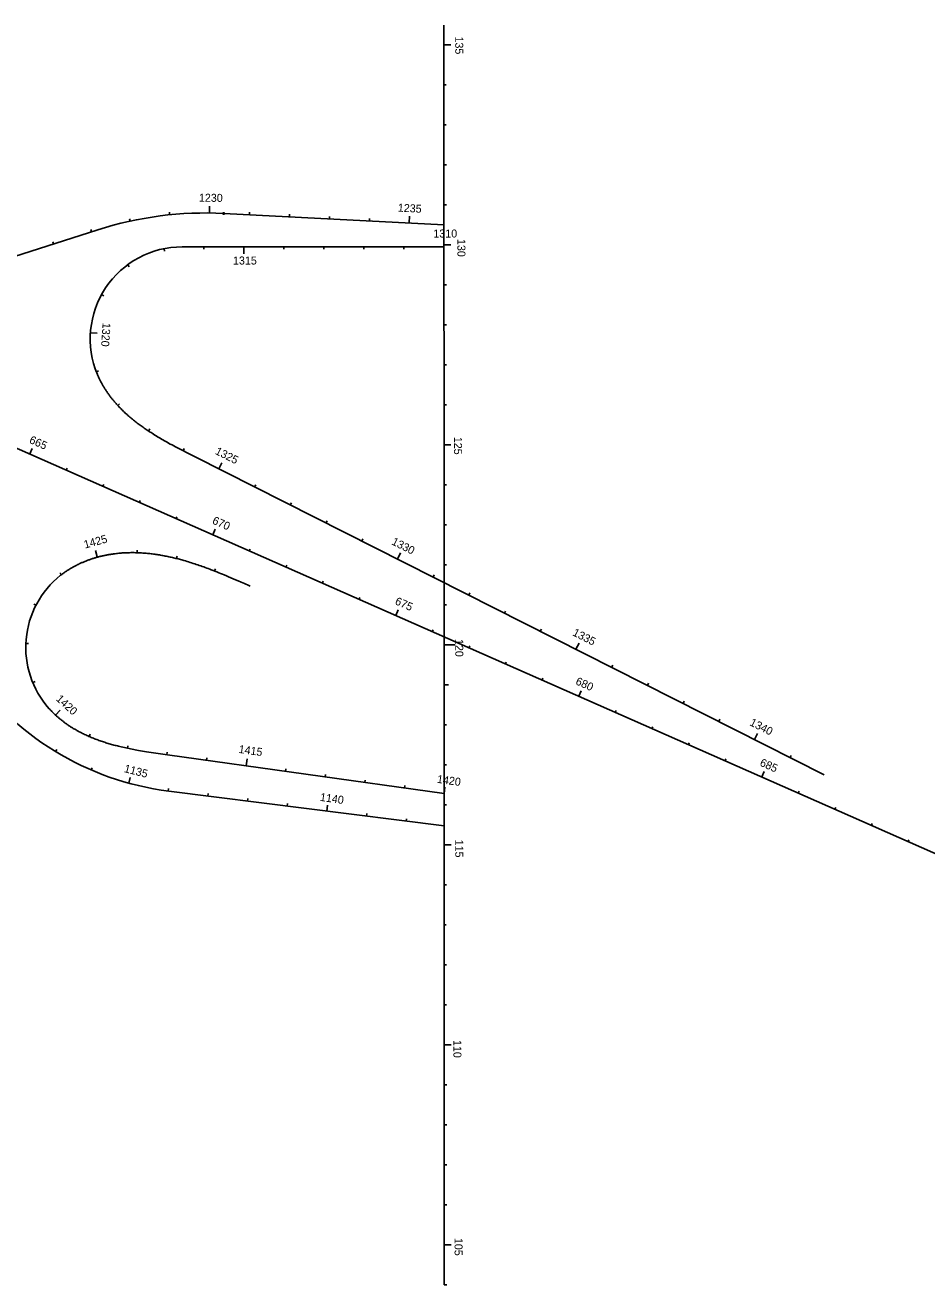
# Model space of a CAD drawing. Extents: x 448091 to 665917, y 1461380 to 1587607.
# Drawn here: x 525049 to 527302, y 1466775 to 1469924 of the extents above; entities that cross this region are included whole.
import ezdxf

# ---------------------------------------------------------------- set-up
doc = ezdxf.new("R2010")
doc.units = 0
doc.layers.add('TextShtNo', color=7, linetype='Continuous')
doc.layers.add('TextTitle', color=7, linetype='Continuous')

msp = doc.modelspace()

# ---------------------------------------------------------------- linework, layer by layer
at = {"layer": 'TextShtNo'}
for p, q in [((526095.6, 1468394.8), (526095, 1469923.7)), ((526095.2, 1469425), (525544.8, 1469453.2)), ((525230.2, 1469412.2), (524834, 1469284.9)), ((525441, 1469369.5), (526095.2, 1469369.8)), ((525230.9, 1469046.2), (525230.1, 1469048)), ((525231.8, 1469044.3), (525230.9, 1469046.2)), ((525232.6, 1469042.5), (525231.8, 1469044.3)), ((525233.5, 1469040.7), (525232.6, 1469042.5)), ((525234.3, 1469038.9), (525233.5, 1469040.7)), ((525235.2, 1469037.1), (525234.3, 1469038.9)), ((525236.1, 1469035.4), (525235.2, 1469037.1)), ((525237, 1469033.6), (525236.1, 1469035.4)), ((525238, 1469031.8), (525237, 1469033.6)), ((525238.9, 1469030), (525238, 1469031.8)), ((525239.9, 1469028.3), (525238.9, 1469030)), ((525240.8, 1469026.5), (525239.9, 1469028.3)), ((525241.8, 1469024.8), (525240.8, 1469026.5)), ((525242.8, 1469023), (525241.8, 1469024.8)), ((525243.8, 1469021.3), (525242.8, 1469023)), ((525244.8, 1469019.6), (525243.8, 1469021.3)), ((525245.9, 1469017.9), (525244.8, 1469019.6)), ((525246.9, 1469016.2), (525245.9, 1469017.9)), ((525248, 1469014.5), (525246.9, 1469016.2)), ((525249.1, 1469012.8), (525248, 1469014.5)), ((525250.2, 1469011.1), (525249.1, 1469012.8)), ((525251.3, 1469009.4), (525250.2, 1469011.1)), ((525252.4, 1469007.8), (525251.3, 1469009.4)), ((525253.5, 1469006.1), (525252.4, 1469007.8)), ((525254.6, 1469004.5), (525253.5, 1469006.1)), ((525255.8, 1469002.8), (525254.6, 1469004.5)), ((525256.9, 1469001.2), (525255.8, 1469002.8)), ((525258.1, 1468999.6), (525256.9, 1469001.2)), ((525259.3, 1468998), (525258.1, 1468999.6)), ((525260.5, 1468996.4), (525259.3, 1468998)), ((525261.7, 1468994.8), (525260.5, 1468996.4)), ((525262.9, 1468993.2), (525261.7, 1468994.8)), ((525264.2, 1468991.6), (525262.9, 1468993.2)), ((525265.4, 1468990), (525264.2, 1468991.6)), ((525266.6, 1468988.5), (525265.4, 1468990)), ((525267.9, 1468986.9), (525266.6, 1468988.5)), ((525269.2, 1468985.4), (525267.9, 1468986.9)), ((525270.5, 1468983.8), (525269.2, 1468985.4)), ((525271.7, 1468982.3), (525270.5, 1468983.8)), ((525273, 1468980.8), (525271.7, 1468982.3)), ((525274.4, 1468979.3), (525273, 1468980.8)), ((525275.7, 1468977.8), (525274.4, 1468979.3)), ((525277, 1468976.3), (525275.7, 1468977.8)), ((525278.3, 1468974.8), (525277, 1468976.3)), ((525279.7, 1468973.3), (525278.3, 1468974.8)), ((525281.7, 1468971.1), (525279.7, 1468973.3)), ((525283.8, 1468968.9), (525281.7, 1468971.1)), ((525285.9, 1468966.8), (525283.8, 1468968.9)), ((525288, 1468964.6), (525285.9, 1468966.8)), ((525290.1, 1468962.5), (525288, 1468964.6)), ((525292.2, 1468960.4), (525290.1, 1468962.5)), ((525294.4, 1468958.3), (525292.2, 1468960.4)), ((525296.6, 1468956.2), (525294.4, 1468958.3)), ((525298.7, 1468954.2), (525296.6, 1468956.2)), ((525300.9, 1468952.2), (525298.7, 1468954.2)), ((525303.2, 1468950.1), (525300.9, 1468952.2)), ((525305.4, 1468948.1), (525303.2, 1468950.1)), ((525307.7, 1468946.2), (525305.4, 1468948.1)), ((525309.9, 1468944.2), (525307.7, 1468946.2)), ((525312.2, 1468942.3), (525309.9, 1468944.2)), ((525314.5, 1468940.3), (525312.2, 1468942.3)), ((525316.8, 1468938.4), (525314.5, 1468940.3)), ((525319.1, 1468936.5), (525316.8, 1468938.4)), ((525321.5, 1468934.6), (525319.1, 1468936.5)), ((525323.8, 1468932.8), (525321.5, 1468934.6)), ((525326.2, 1468930.9), (525323.8, 1468932.8)), ((525328.6, 1468929.1), (525326.2, 1468930.9)), ((525331, 1468927.3), (525328.6, 1468929.1)), ((525333.4, 1468925.5), (525331, 1468927.3)), ((525335.8, 1468923.7), (525333.4, 1468925.5)), ((525338.2, 1468922), (525335.8, 1468923.7)), ((525340.7, 1468920.2), (525338.2, 1468922)), ((525343.1, 1468918.5), (525340.7, 1468920.2)), ((525345.6, 1468916.7), (525343.1, 1468918.5)), ((525348, 1468915), (525345.6, 1468916.7)), ((525350.5, 1468913.3), (525348, 1468915)), ((525353, 1468911.7), (525350.5, 1468913.3)), ((525355.5, 1468910), (525353, 1468911.7)), ((525358, 1468908.3), (525355.5, 1468910)), ((525360.5, 1468906.7), (525358, 1468908.3)), ((525363, 1468905.1), (525360.5, 1468906.7)), ((525365.5, 1468903.5), (525363, 1468905.1)), ((525368.9, 1468901.3), (525365.5, 1468903.5)), ((524956.6, 1468897.4), (528389.9, 1467382.4)), ((525372.3, 1468899.2), (525368.9, 1468901.3)), ((525375.7, 1468897.1), (525372.3, 1468899.2)), ((525379.2, 1468895), (525375.7, 1468897.1)), ((525382.6, 1468893), (525379.2, 1468895)), ((525386, 1468891), (525382.6, 1468893)), ((525389.5, 1468888.9), (525386, 1468891)), ((525392.9, 1468886.9), (525389.5, 1468888.9)), ((525396.4, 1468885), (525392.9, 1468886.9)), ((525399.9, 1468883), (525396.4, 1468885)), ((525403.4, 1468881), (525399.9, 1468883)), ((525406.9, 1468879.1), (525403.4, 1468881)), ((525411.3, 1468876.7), (525406.9, 1468879.1)), ((525415.7, 1468874.3), (525411.3, 1468876.7)), ((525420.1, 1468872), (525415.7, 1468874.3)), ((525424.5, 1468869.6), (525420.1, 1468872)), ((525471.7, 1468845.4), (525424.5, 1468869.6)), ((527046, 1468049.8), (525471.7, 1468845.4)), ((526096.2, 1466774.9), (526095.6, 1468394.8)), ((525111.2, 1468212.2), (525109.9, 1468213.7)), ((525112.6, 1468210.7), (525111.2, 1468212.2)), ((525114, 1468209.3), (525112.6, 1468210.7)), ((525115.4, 1468207.8), (525114, 1468209.3)), ((525116.8, 1468206.4), (525115.4, 1468207.8)), ((525118.2, 1468205), (525116.8, 1468206.4)), ((525119.6, 1468203.6), (525118.2, 1468205)), ((525121.1, 1468202.2), (525119.6, 1468203.6)), ((525122.5, 1468200.8), (525121.1, 1468202.2)), ((525124, 1468199.4), (525122.5, 1468200.8)), ((525125.5, 1468198.1), (525124, 1468199.4)), ((525127, 1468196.7), (525125.5, 1468198.1)), ((525128.4, 1468195.4), (525127, 1468196.7)), ((525129.9, 1468194.1), (525128.4, 1468195.4)), ((525131.5, 1468192.8), (525129.9, 1468194.1)), ((525133, 1468191.5), (525131.5, 1468192.8)), ((525134.5, 1468190.2), (525133, 1468191.5)), ((525136.1, 1468188.9), (525134.5, 1468190.2)), ((525137.6, 1468187.7), (525136.1, 1468188.9)), ((525139.2, 1468186.4), (525137.6, 1468187.7)), ((525140.8, 1468185.2), (525139.2, 1468186.4)), ((525142.3, 1468183.9), (525140.8, 1468185.2)), ((525143.9, 1468182.7), (525142.3, 1468183.9)), ((525145.5, 1468181.5), (525143.9, 1468182.7)), ((525147.1, 1468180.3), (525145.5, 1468181.5)), ((525148.8, 1468179.1), (525147.1, 1468180.3)), ((525150.4, 1468178), (525148.8, 1468179.1)), ((525152, 1468176.8), (525150.4, 1468178)), ((525153.7, 1468175.7), (525152, 1468176.8)), ((525155.3, 1468174.5), (525153.7, 1468175.7)), ((525157, 1468173.4), (525155.3, 1468174.5)), ((525158.6, 1468172.3), (525157, 1468173.4)), ((525160.3, 1468171.2), (525158.6, 1468172.3)), ((525162, 1468170.1), (525160.3, 1468171.2)), ((525163.7, 1468169.1), (525162, 1468170.1)), ((525165.4, 1468168), (525163.7, 1468169.1)), ((525167.1, 1468166.9), (525165.4, 1468168)), ((525168.8, 1468165.9), (525167.1, 1468166.9)), ((525170.5, 1468164.9), (525168.8, 1468165.9)), ((525172.2, 1468163.9), (525170.5, 1468164.9)), ((525173.9, 1468162.8), (525172.2, 1468163.9)), ((525175.7, 1468161.9), (525173.9, 1468162.8)), ((525177.4, 1468160.9), (525175.7, 1468161.9)), ((525179.2, 1468159.9), (525177.4, 1468160.9)), ((525180.9, 1468158.9), (525179.2, 1468159.9)), ((525183.6, 1468157.5), (525180.9, 1468158.9)), ((525186.2, 1468156.1), (525183.6, 1468157.5)), ((525188.9, 1468154.7), (525186.2, 1468156.1)), ((525191.6, 1468153.4), (525188.9, 1468154.7)), ((525194.2, 1468152), (525191.6, 1468153.4)), ((525196.9, 1468150.7), (525194.2, 1468152)), ((525199.7, 1468149.5), (525196.9, 1468150.7)), ((525202.4, 1468148.2), (525199.7, 1468149.5)), ((525205.1, 1468147), (525202.4, 1468148.2)), ((525207.9, 1468145.8), (525205.1, 1468147)), ((525210.6, 1468144.6), (525207.9, 1468145.8)), ((525213.4, 1468143.4), (525210.6, 1468144.6)), ((525216.1, 1468142.2), (525213.4, 1468143.4)), ((525218.9, 1468141.1), (525216.1, 1468142.2)), ((525221.7, 1468140), (525218.9, 1468141.1)), ((525224.5, 1468138.9), (525221.7, 1468140)), ((525227.3, 1468137.9), (525224.5, 1468138.9)), ((525230.1, 1468136.8), (525227.3, 1468137.9)), ((525233, 1468135.8), (525230.1, 1468136.8)), ((525235.8, 1468134.8), (525233, 1468135.8)), ((525238.6, 1468133.8), (525235.8, 1468134.8)), ((525241.5, 1468132.9), (525238.6, 1468133.8)), ((525244.3, 1468131.9), (525241.5, 1468132.9)), ((525247.2, 1468131), (525244.3, 1468131.9)), ((525250, 1468130.1), (525247.2, 1468131)), ((525252.9, 1468129.2), (525250, 1468130.1)), ((525255.8, 1468128.3), (525252.9, 1468129.2)), ((525258.6, 1468127.5), (525255.8, 1468128.3)), ((525261.5, 1468126.6), (525258.6, 1468127.5)), ((525264.4, 1468125.8), (525261.5, 1468126.6)), ((525267.3, 1468125), (525264.4, 1468125.8)), ((525270.2, 1468124.2), (525267.3, 1468125)), ((525273.1, 1468123.4), (525270.2, 1468124.2)), ((525276, 1468122.7), (525273.1, 1468123.4)), ((525278.9, 1468121.9), (525276, 1468122.7)), ((525281.8, 1468121.2), (525278.9, 1468121.9)), ((525284.7, 1468120.5), (525281.8, 1468121.2)), ((525288.6, 1468119.6), (525284.7, 1468120.5)), ((525292.5, 1468118.7), (525288.6, 1468119.6)), ((525296.4, 1468117.8), (525292.5, 1468118.7)), ((525300.3, 1468116.9), (525296.4, 1468117.8)), ((525304.2, 1468116.1), (525300.3, 1468116.9)), ((525308.1, 1468115.3), (525304.2, 1468116.1)), ((525312.1, 1468114.5), (525308.1, 1468115.3)), ((525316, 1468113.7), (525312.1, 1468114.5)), ((525319.9, 1468113), (525316, 1468113.7)), ((525323.8, 1468112.2), (525319.9, 1468113)), ((525327.8, 1468111.5), (525323.8, 1468112.2)), ((525331.7, 1468110.8), (525327.8, 1468111.5)), ((525336.6, 1468110), (525331.7, 1468110.8)), ((525341.6, 1468109.1), (525336.6, 1468110)), ((525346.5, 1468108.3), (525341.6, 1468109.1)), ((525351.4, 1468107.5), (525346.5, 1468108.3)), ((525403.9, 1468099.8), (525351.4, 1468107.5)), ((526095.7, 1468002.8), (525403.9, 1468099.8)), ((526095.7, 1467922.1), (525407.4, 1468009))]:
    msp.add_line(p, q, dxfattribs=at)
for points in [[(525230.1, 1469048), (525229.3, 1469049.8), (525229, 1469050.8)], [(525137, 1468548.5), (525138.6, 1468549.7), (525140.2, 1468550.9), (525141.8, 1468552.1), (525143.4, 1468553.3), (525145.1, 1468554.5), (525146.7, 1468555.6), (525148.4, 1468556.8), (525150, 1468557.9), (525151.7, 1468559), (525153.4, 1468560.1), (525155.1, 1468561.2), (525156.8, 1468562.3), (525158.5, 1468563.4), (525160.2, 1468564.4), (525161.9, 1468565.5), (525163.7, 1468566.5), (525165.4, 1468567.5), (525167.2, 1468568.5), (525168.9, 1468569.5), (525170.7, 1468570.4), (525172.4, 1468571.4), (525174.2, 1468572.3), (525176, 1468573.2), (525177.8, 1468574.2), (525179.6, 1468575.1), (525181.4, 1468575.9), (525183.2, 1468576.8), (525185, 1468577.7), (525186.8, 1468578.5), (525188.7, 1468579.3), (525190.5, 1468580.1), (525192.4, 1468580.9), (525194.2, 1468581.7), (525196, 1468582.5), (525197.9, 1468583.3), (525199.8, 1468584), (525201.6, 1468584.8), (525203.5, 1468585.5), (525205.4, 1468586.2), (525207.3, 1468586.9), (525209.2, 1468587.5), (525211.1, 1468588.2), (525212.9, 1468588.9), (525214.9, 1468589.5), (525216.8, 1468590.1), (525218.7, 1468590.7), (525220.6, 1468591.3), (525222.5, 1468591.9), (525224.4, 1468592.5), (525226.3, 1468593), (525228.3, 1468593.6), (525230.2, 1468594.1), (525232.1, 1468594.6), (525234.1, 1468595.1), (525236, 1468595.6), (525238, 1468596.1), (525239.9, 1468596.6), (525241.9, 1468597), (525243.8, 1468597.5), (525245.8, 1468597.9), (525247.7, 1468598.3), (525249.7, 1468598.7), (525251.7, 1468599.1), (525253.6, 1468599.5), (525255.6, 1468599.8), (525257.6, 1468600.2), (525259.5, 1468600.5), (525261.5, 1468600.8), (525263.5, 1468601.2), (525265.5, 1468601.5), (525267.5, 1468601.7), (525269.4, 1468602), (525271.4, 1468602.3), (525273.4, 1468602.5), (525276.4, 1468602.9), (525279.4, 1468603.2), (525282.4, 1468603.5), (525285.4, 1468603.8), (525288.4, 1468604), (525291.3, 1468604.3), (525294.3, 1468604.4), (525297.3, 1468604.6), (525300.3, 1468604.8), (525303.3, 1468604.9), (525306.3, 1468605), (525309.3, 1468605), (525312.3, 1468605.1), (525315.3, 1468605.1), (525318.3, 1468605.1), (525321.3, 1468605.1), (525324.3, 1468605), (525327.3, 1468604.9), (525330.3, 1468604.8), (525333.3, 1468604.7), (525336.3, 1468604.6), (525339.3, 1468604.4), (525342.3, 1468604.2), (525345.3, 1468604), (525348.3, 1468603.8), (525351.3, 1468603.5)], [(525351.3, 1468603.5), (525354.3, 1468603.2), (525357.3, 1468602.9), (525360.3, 1468602.6), (525363.2, 1468602.3), (525366.2, 1468601.9), (525369.2, 1468601.5), (525372.2, 1468601.1), (525375.1, 1468600.7), (525378.1, 1468600.3), (525381.1, 1468599.8), (525384, 1468599.3), (525387, 1468598.8), (525389.9, 1468598.3), (525392.9, 1468597.8), (525395.8, 1468597.2), (525398.8, 1468596.7), (525401.7, 1468596.1), (525404.7, 1468595.5), (525407.6, 1468594.9), (525410.5, 1468594.2), (525413.5, 1468593.6), (525416.4, 1468592.9), (525419.3, 1468592.2), (525422.2, 1468591.5), (525425.1, 1468590.8), (525428.1, 1468590.1), (525431, 1468589.3), (525433.9, 1468588.6), (525436.8, 1468587.8), (525439.7, 1468587), (525442.5, 1468586.2), (525445.4, 1468585.4), (525449.3, 1468584.3), (525453.1, 1468583.1), (525456.9, 1468582), (525460.8, 1468580.8), (525464.6, 1468579.6), (525468.4, 1468578.4), (525472.2, 1468577.1), (525476, 1468575.9), (525479.8, 1468574.6), (525483.6, 1468573.3), (525487.3, 1468572), (525491.1, 1468570.7), (525494.9, 1468569.3), (525498.6, 1468567.9), (525502.4, 1468566.6), (525506.1, 1468565.2), (525509.9, 1468563.8), (525513.6, 1468562.3), (525518.2, 1468560.5), (525522.9, 1468558.7), (525527.5, 1468556.9), (525532.2, 1468555), (525536.8, 1468553.1), (525541.4, 1468551.2), (525546, 1468549.3), (525551.6, 1468547), (525557.1, 1468544.7), (525562.6, 1468542.3), (525568.2, 1468540), (525574.6, 1468537.2), (525581, 1468534.4), (525588.3, 1468531.2), (525596.6, 1468527.6), (525607.6, 1468522.7), (525611.2, 1468521.1)], [(525109.9, 1468213.7), (525108.5, 1468215.1), (525107.9, 1468215.9)]]:
    msp.add_lwpolyline(points, dxfattribs=at)
for centre, radius, start, end in [((525499.6, 1468572.9), 881.4, 87.0627, 107.8025), ((525441.1, 1469139.6), 230, 90.0209, 202.709), ((525280, 1468368.4), 230, 128.4671, 221.5395), ((525497.1, 1468719.5), 716.2, 214.0543, 262.8036)]:
    msp.add_arc(centre, radius, start, end, dxfattribs=at)
at = {"layer": 'TextTitle'}
for p, q in [((526112.3, 1469874.8), (526095, 1469874.8)), ((526101.2, 1469774.8), (526095.1, 1469774.8)), ((526101.2, 1469674.8), (526095.1, 1469674.8)), ((526101.3, 1469574.8), (526095.1, 1469574.8)), ((525509.4, 1469454.3), (525509.5, 1469471.6)), ((526101.3, 1469474.8), (526095.2, 1469474.8)), ((525310.8, 1469433.9), (525309.5, 1469439.9)), ((525409.5, 1469449.7), (525408.9, 1469455.9)), ((525609.2, 1469449.9), (525609.5, 1469456)), ((525709.1, 1469444.8), (525709.4, 1469450.9)), ((525808.9, 1469439.6), (525809.3, 1469445.8)), ((525908.8, 1469434.5), (525909.1, 1469440.6)), ((526008.7, 1469429.4), (526009.5, 1469446.6)), ((525214.5, 1469407.1), (525212.6, 1469413)), ((525119.3, 1469376.6), (525117.4, 1469382.4)), ((525395.6, 1469365), (525396.8, 1469359)), ((525495.3, 1469369.6), (525495.3, 1469363.5)), ((525595.2, 1469369.6), (525595.2, 1469352.4)), ((525695.2, 1469369.6), (525695.2, 1469363.5)), ((525795.2, 1469369.7), (525795.2, 1469363.5)), ((525895.2, 1469369.7), (525895.2, 1469363.6)), ((525995.2, 1469369.7), (525995.2, 1469363.6)), ((526112.4, 1469374.8), (526095.2, 1469374.8)), ((526095.2, 1469369.7), (526095.2, 1469363.6)), ((525304.8, 1469324.8), (525308.4, 1469319.9)), ((525239.5, 1469250.2), (525244.8, 1469247.3)), ((526101.4, 1469274.8), (526095.2, 1469274.8)), ((525211.6, 1469155), (525228.8, 1469153.8)), ((526101.4, 1469174.8), (526095.3, 1469174.8)), ((526101.4, 1469074.8), (526095.3, 1469074.8)), ((525232.1, 1469059.4), (525226.4, 1469057.2)), ((525280, 1468973), (525284.5, 1468977.1)), ((526101.5, 1468974.8), (526095.3, 1468974.8)), ((525356.7, 1468909.2), (525360.1, 1468914.3)), ((526112.6, 1468874.8), (526095.4, 1468874.8)), ((525065.8, 1468865.6), (525059.8, 1468851.8)), ((525443.6, 1468859.8), (525446.2, 1468865.1)), ((525153.3, 1468816.1), (525151.3, 1468811.5)), ((525532.7, 1468814.5), (525540.4, 1468829.9)), ((525244.8, 1468775.7), (525242.8, 1468771.1)), ((525621.9, 1468769.4), (525624.7, 1468774.9)), ((526101.5, 1468774.8), (526095.4, 1468774.8)), ((525336.3, 1468735.3), (525334.2, 1468730.7)), ((525711.2, 1468724.3), (525713.9, 1468729.8)), ((525427.8, 1468694.9), (525425.7, 1468690.4)), ((525800.4, 1468679.2), (525803.2, 1468684.7)), ((525523.3, 1468663.7), (525517.2, 1468650)), ((526101.6, 1468674.8), (526095.5, 1468674.8)), ((525889.7, 1468634.1), (525892.4, 1468639.6)), ((525228.8, 1468594.4), (525224.3, 1468610.4)), ((525328.1, 1468605.1), (525328.3, 1468611)), ((525426.8, 1468590.4), (525428.3, 1468596.3)), ((525610.7, 1468614.2), (525608.7, 1468609.6)), ((525978.9, 1468589), (525986.6, 1468604.5)), ((525521.8, 1468559.3), (525524, 1468564.8)), ((525702.2, 1468573.8), (525700.2, 1468569.2)), ((526101.6, 1468574.8), (526095.5, 1468574.8)), ((525139.1, 1468550.2), (525135.4, 1468555)), ((525793.7, 1468533.5), (525791.7, 1468528.9)), ((526068.2, 1468543.9), (526070.9, 1468549.4)), ((526157.4, 1468498.8), (526160.2, 1468504.3)), ((525075.7, 1468473.9), (525070.2, 1468476.7)), ((525885.2, 1468493.1), (525883.2, 1468488.5)), ((526101.6, 1468474.8), (526095.5, 1468474.8)), ((525980.7, 1468461.9), (525974.7, 1468448.1)), ((526246.7, 1468453.7), (526249.5, 1468459.2)), ((526068.2, 1468412.3), (526066.2, 1468407.8)), ((526335.9, 1468408.6), (526338.7, 1468414.1)), ((525056.4, 1468377.8), (525050.2, 1468378)), ((526122.8, 1468374.8), (526095.6, 1468374.8)), ((526159.7, 1468372), (526157.6, 1468367.4)), ((526425.2, 1468363.5), (526432.9, 1468378.9)), ((526251.2, 1468331.6), (526249.1, 1468327)), ((526514.4, 1468318.4), (526517.2, 1468323.8)), ((525073.2, 1468282.7), (525067.6, 1468280.3)), ((526106.7, 1468274.8), (526095.6, 1468274.8)), ((526342.6, 1468291.2), (526340.6, 1468286.7)), ((526603.7, 1468273.3), (526606.4, 1468278.7)), ((526438.2, 1468260), (526432.1, 1468246.3)), ((525136.2, 1468211.7), (525124.5, 1468199)), ((526525.6, 1468210.5), (526523.6, 1468205.9)), ((526692.9, 1468228.2), (526695.7, 1468233.6)), ((526782.1, 1468183.1), (526784.9, 1468188.6)), ((525210.8, 1468151.2), (525208.4, 1468145.5)), ((526101.8, 1468174.8), (526095.6, 1468174.8)), ((526617.1, 1468170.1), (526615.1, 1468165.5)), ((526871.4, 1468138), (526879.1, 1468153.4)), ((525305.1, 1468122.2), (525303.9, 1468116.2)), ((526708.6, 1468129.7), (526706.6, 1468125.2)), ((525127.8, 1468113), (525124.6, 1468107.8)), ((525403.3, 1468106.1), (525402.5, 1468100)), ((525502.4, 1468092.2), (525501.6, 1468086.1)), ((525603, 1468089.3), (525600.5, 1468072.2)), ((526800.1, 1468089.4), (526798.1, 1468084.8)), ((526960.6, 1468092.9), (526963.4, 1468098.4)), ((525215.8, 1468067.5), (525213.4, 1468061.9)), ((525700.4, 1468064.5), (525699.6, 1468058.4)), ((526101.8, 1468074.8), (526095.7, 1468074.8)), ((526895.6, 1468058.1), (526889.6, 1468044.4)), ((525311.3, 1468043), (525307.7, 1468028.8)), ((525799.5, 1468050.6), (525798.6, 1468044.5)), ((525898.5, 1468036.7), (525897.6, 1468030.6)), ((525997.5, 1468022.8), (525996.7, 1468016.7)), ((525406.4, 1468015.3), (525405.6, 1468009.2)), ((525504.8, 1467996.7), (525505.6, 1468002.8)), ((525604, 1467984.1), (525604.8, 1467990.2)), ((526097.8, 1468018.8), (526095.7, 1468002.8)), ((526983.1, 1468008.6), (526981, 1468004.1)), ((525703.2, 1467971.6), (525703.9, 1467977.7)), ((525802.4, 1467959.1), (525804.1, 1467973.6)), ((526101.8, 1467974.8), (526095.7, 1467974.8)), ((527074.5, 1467968.3), (527072.5, 1467963.7)), ((525901.6, 1467946.6), (525902.5, 1467952.7)), ((526000.8, 1467934), (526001.6, 1467940.1)), ((527166, 1467927.9), (527164, 1467923.3)), ((526113, 1467874.8), (526095.7, 1467874.8)), ((527257.5, 1467887.5), (527255.5, 1467882.9)), ((526101.9, 1467774.9), (526095.8, 1467774.9)), ((526100.4, 1467674.9), (526095.8, 1467674.9)), ((526102, 1467574.9), (526095.8, 1467574.9)), ((526102, 1467474.9), (526095.9, 1467474.9)), ((526113.2, 1467374.9), (526095.9, 1467374.9)), ((526102.1, 1467274.9), (526096, 1467274.9)), ((526102.1, 1467174.9), (526096, 1467174.9)), ((526102.2, 1467074.9), (526096, 1467074.9)), ((526102.2, 1466974.9), (526096.1, 1466974.9)), ((526113.3, 1466874.9), (526096.1, 1466874.9)), ((526102.3, 1466774.9), (526096.1, 1466774.9))]:
    msp.add_line(p, q, dxfattribs=at)
msp.add_circle((525544.6, 1469453), 2, dxfattribs=at)

# ---------------------------------------------------------------- texts
for s, rotation, p in [('135', 270.0207, (526123.5, 1469895.4)), ('1230', 359.4192, (525482.7, 1469482.5)), ('1235', 357.062, (525979.6, 1469457.7)), ('1310', 0.0207, (526068.8, 1469392.9)), ('130', 270.0207, (526128.9, 1469389.2)), ('1315', 0.0207, (525567.9, 1469325.4)), ('1320', 266.1593, (525242.2, 1469180.2)), ('665', 336.1895, (525057, 1468880)), ('125', 270.0207, (526120.5, 1468894.7)), ('1325', 333.1896, (525521.7, 1468852.6)), ('670', 336.1895, (525514.4, 1468678.5)), ('1425', 15.5005, (525198.1, 1468615.2)), ('1330', 333.1896, (525962.6, 1468626.6)), ('675', 336.1895, (525971.2, 1468476.8)), ('1335', 333.1896, (526415, 1468399.1)), ('120', 270.0207, (526123.6, 1468389.3)), ('680', 336.1895, (526422.5, 1468276.6)), ('1420', 317.2121, (525123.9, 1468237.6)), ('1340', 333.1896, (526857.8, 1468174.4)), ('1415', 352.0207, (525581.2, 1468104.7)), ('685', 336.1895, (526883.1, 1468073.3)), ('1135', 345.5942, (525294.4, 1468056.8)), ('1420', 352.0207, (526077, 1468029.9)), ('1140', 352.0206, (525784.5, 1467984.8)), ('115', 270.0207, (526123.6, 1467887.7)), ('110', 270.0207, (526118.9, 1467386.8)), ('105', 270.0207, (526121.8, 1466892.2))]:
    msp.add_text(s, height=20, rotation=rotation, dxfattribs=at).set_placement(p)

doc.saveas('drawing.dxf')
